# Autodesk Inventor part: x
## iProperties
Shininess: 64.0
Length Units: 11269
Angle Units: 11279
Time Units: 11290
Mass Units: 11283
Length Display Precision: 3
Angle Display Precision: 2
Compacted: True
Part Number: x
Document SubType Name: Modellieren
Created: 2004-07
Material: Standard
Designer: ThMu
Manufacturer: Standard
Standards Organization: Custom
Density: 0.0
Volumn: 0.0
Area: 0.0
PropertySet Name: Model Information
Control State: 0
Master: False
Checked Out: False
Author: ThMu
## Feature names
1. Drehung1 [Revolution]
2. Erhebung1
3. ExtrusionAbwicklung1
